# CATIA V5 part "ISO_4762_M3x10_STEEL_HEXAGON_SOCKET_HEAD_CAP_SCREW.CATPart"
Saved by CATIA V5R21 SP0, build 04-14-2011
Part number: ISO 4762 SCREW M3x10 STEEL HEXAGON SOCKET HEAD CAP
Publications: "Mating Face", "Axis"
Bounding box of the stored display mesh (mm): x -10 to 3, y -2.75 to 2.75, z -2.741 to 2.741
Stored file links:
  D:\FRANCE\Stage\CAO\ISO_4762_M3x10_STEEL_HEXAGON_SOCKET_HEAD_CAP_SCREW.CATPart
  C:\Program Files (x86)\Dassault Systemes\B21\intel_a\startup\components\MechanicalStandardParts\EN_Standards\Design_Tables\EN_ISO_4762_HEXAGON_SOCKET_HEAD_CAP_SCREW.txt
  C:\Program Files (x86)\Dassault Systemes\B21\intel_a\startup\components\MechanicalStandardParts\ISO_Standards\Design_Tables\ISO_4762_HEXAGON_SOCKET_HEAD_CAP_SCREW.txt
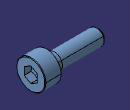
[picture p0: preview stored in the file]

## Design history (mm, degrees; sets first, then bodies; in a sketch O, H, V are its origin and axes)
Parameters
  d_dia = 3 mm
  l_nom = 10 mm
  k_head_depth_max = 3 mm
  s_nom = 2.5 mm
  r_min = 0.1 mm
  ds_max = 3 mm
  e = 2.873 mm
  t_min = 1.3 mm
  p_pitch = 0.5 mm
  Threading = 8.5 mm
  dk_max = 5.5 mm
Body1 "PartBody" (main body)
  Sketch1 on yz-plane, origin (0, 0, 0), H (0, 1, 0), V (0, 0, 1)
    circle A1 centre (0, 0) radius 2.75
    radius A1 = 2.75 {= dk_max /2}
  Pad1: profile Sketch1, direction (1, 0, 0), length 3 {= k_head_depth_max}
  Fillet1: radius 0.1 {= r_min}, on edge [face of Pad1 | face of Pad1]
  Body2
    Sketch2 on face of Pad1, origin (3, 0, 0), H (0, 1, 0), V (0, 0, 1)
      point P1 (1.25, -0.7217)
      point P2 (1.25, 0.7217)
      point P3 (0, 1.4434)
      point P4 (-1.25, 0.7217)
      point P5 (-1.25, -0.7217)
      point P6 (0, -1.4434)
      point P7 (1.25, 0)
      line L1 (1.25, -0.7217) -> (1.25, 0.7217)
      line L2 (1.25, 0.7217) -> (0, 1.4434)
      line L3 (0, 1.4434) -> (-1.25, 0.7217)
      line L4 (-1.25, 0.7217) -> (-1.25, -0.7217)
      line L5 (-1.25, -0.7217) -> (0, -1.4434)
      line L6 (0, -1.4434) -> (1.25, -0.7217)
      construction line L7 (0, 0) -> (1.25, 0)
      construction circle A1 centre (0, 0) radius 1.4434
      construction arc A2 centre (-1.25, -0.7217) radius 1.4434 from (-1.25, 0.7217) to (0, -1.4434) cw
      construction arc A3 centre (1.25, 0.7217) radius 1.4434 from (0, 1.4434) to (1.25, -0.7217) ccw
      point P8 (-1.25, -0.7217)
      point P9 (1.25, 0.7217)
      distance L1 L4 = 2.5 {= s_nom}
      horizontal: L7 H
      coincidence: A1 P1, A1 P2, A1 P3, A1 P4, A1 P5, A1 P6, A2 P4, A2 P6, A2 O, P8 P5, A3 P3, A3 P1, A3 O, P9 P2
      midpoint: P7 L1
    Pad2: profile Sketch2, direction (-1, 0, 0), length 2.128 {= t_min +(e /3.47)}
    Body3
      Sketch3 on zx-plane, origin (0, 0, 0), H (-1, 0, 0), V (0, 0, 1)
        point P1 (-0.8706, 0)
        line L1 (-0.8706, 0) -> (-1.7, 1.4365)
        line L2 (-1.7, 1.4365) -> (-3, 1.4365)
        line L3 (-3, 1.4365) -> (-3, 0)
        axis line L4 (-46.2384, 0) -> (26.3409, 0)
        reference projected line E1 (-3, -6.9227) -> (-3, 6.9227) from edge [face of Pad2 | face of Pad2]
        length L2 = 1.3 {= t_min}
        angle L1 L4 = 60
        distance L2 L4 = 1.4365 {= e /2}
        horizontal: L2 H, L4 H
        perpendicularity: L3 L2
        fix: L4
        coincidence: L3 E1, P1 L4
      Shaft1: profile Sketch3, axis Sketch3.L4, angle 360
    Intersect1: tool Body3
  Remove1: tool Body2
  Sketch4 on xy-plane, origin (0, 0, 0), H (1, 0, 0), V (0, 1, 0)
    line L1 (0, 0) -> (0, 1.5)
    line L2 (0, 1.5) -> (-1.5, 1.5)
    line L3 (-1.5, 1.5) -> (-1.5, 1.4634)
    line L4 (-1.5, 1.4634) -> (-10, 1.4634)
    line L5 (-10, 1.4634) -> (-10, 0)
    axis line L6 (-192.3446, 0) -> (99.1594, 0)
    distance L5 L1 = 10 {= l_nom}
    distance L3 L5 = 8.5 {= Threading}
    distance L2 L6 = 1.5 {= ds_max /2}
    distance L4 L6 = 1.4634 {= d_dia /2.05}
    vertical: L1 V, L3 V, L5 V
    horizontal: L2 H, L4 H, L6 H
    fix: L6
  Shaft2: profile Sketch4, axis Sketch4.L6, angle 360
  Fillet2: radius 0.1 {= r_min}, on edge [face of Shaft2 | face of Pad1]
  Chamfer1: length 0.5 {= p_pitch}, angle 45, on edge [face of Shaft2 | face of Shaft2]
  Thread1: diameter 2.9268 {= d_dia /1.025}, depth 8.5 {= Threading}, pitch 1, on face of Shaft2, from face of Shaft2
